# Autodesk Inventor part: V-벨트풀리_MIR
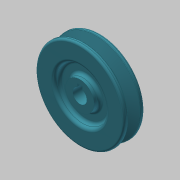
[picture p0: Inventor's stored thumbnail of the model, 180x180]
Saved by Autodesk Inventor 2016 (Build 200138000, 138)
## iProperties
Created: 2019-09
Part Number: V-벨트풀리_MIR
Material: 알루미늄 6061
Document SubType Name: Modeling
Designer: Administrator
Density: 2.71 g/cm^3
Appearance: 알루미늄 - 평지
Author: mduedu
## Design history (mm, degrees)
derived "V-벨트풀리.ipt"
  sketch "스케치1"
    geometry: L1 (10, 0)-(-10, 0) reference; L2 (-10, 0)-(-10, 43.5) reference; L3 (-10, 43.5)-(10, 43.5) reference; L4 (10, 43.5)-(10, 0) reference; L5 (0, 0)-(0, 43.5) reference; L6 (5.976, 43.5)-(2.154, 31) reference; L7 (2.154, 31)-(-2.154, 31) reference; L8 (-2.154, 31)-(-5.976, 43.5) reference; L9 (10, 39)-(-10, 39) reference; 3 further points
  sketch "스케치2"
    geometry: C1 r 14 at (0, 0) reference; C2 r 25 at (0, 0) reference; 1 further point
  sketch "스케치3"
    geometry: L1 (2.5, 6.538)-(-2.5, 6.538) reference; L2 (-2.5, 6.538)-(-2.5, 9.3) reference; L3 (-2.5, 9.3)-(2.5, 9.3) reference; L4 (2.5, 9.3)-(2.5, 6.538) reference; A1 r 7 centre (0, 0) between (2.5, 6.538) and (-2.5, 6.538) reference; 1 further point
feature "솔리드1::V-벨트풀리.ipt"
tag "피쳐 태그1"
node "솔리드1"
